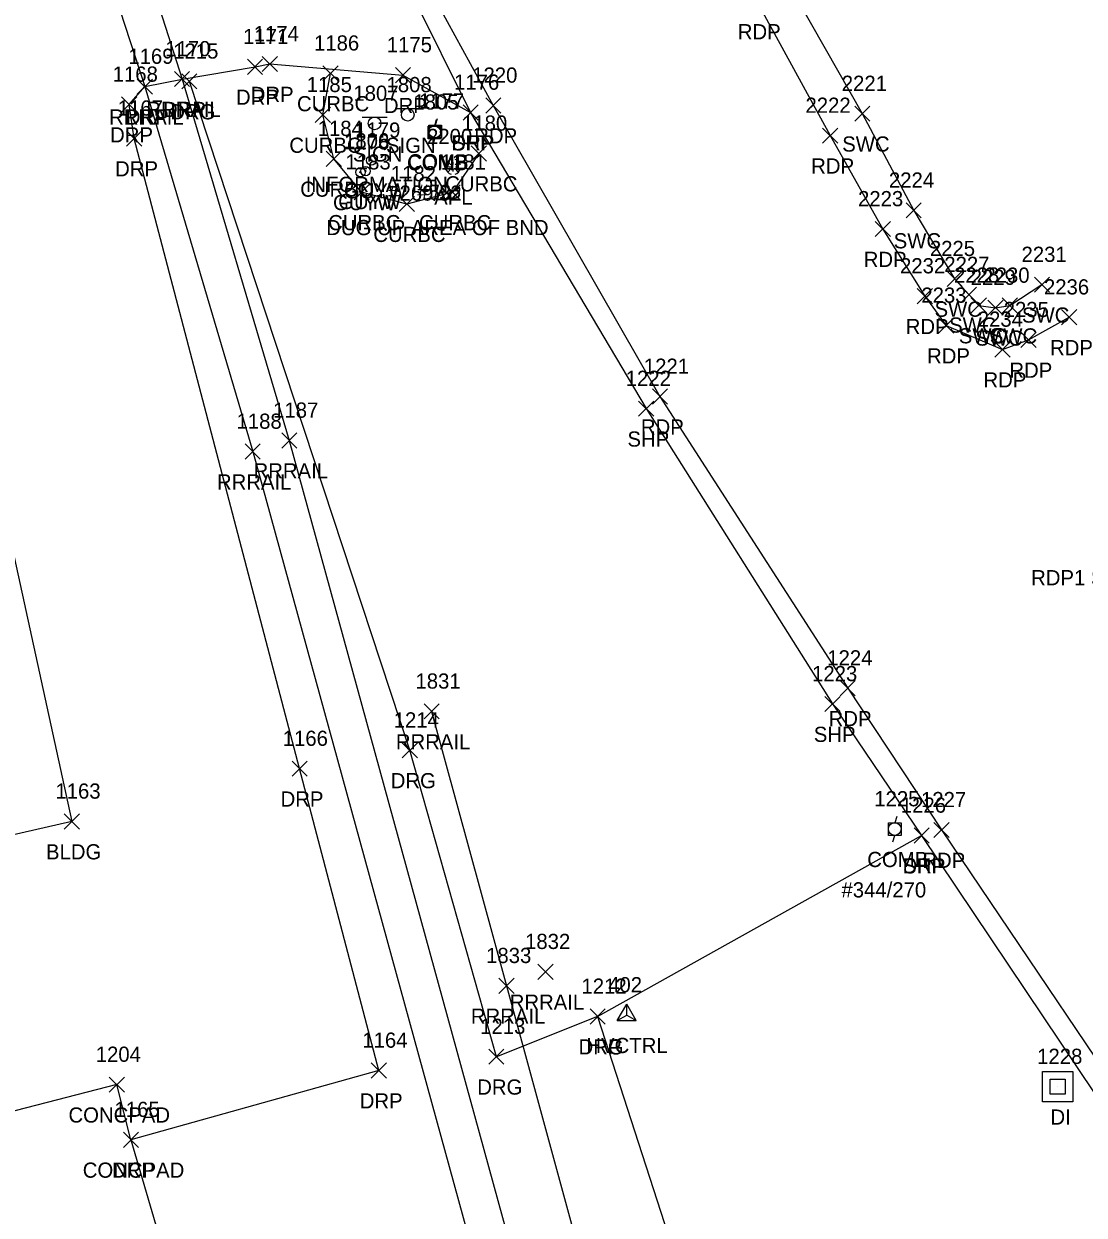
# Model space of a CAD drawing. Extents: x 1635588 to 1637550, y 621583 to 623638.
# Drawn here: x 1636495.2 to 1636634.9, y 622780.1 to 622937 of the extents above; entities that cross this region are included whole.
import ezdxf

# ---------------------------------------------------------------- set-up
doc = ezdxf.new("R2010")
doc.units = 0
for name, color, linetype in [('C_A', 7, 'Continuous'), ('C_I', 7, 'Continuous'), ('CPSM', 7, 'Continuous'), ('D_A', 7, 'Continuous'), ('D_I', 7, 'Continuous'), ('Default', 7, 'Continuous'), ('DS', 7, 'Continuous'), ('L_A', 7, 'Continuous'), ('L_I', 7, 'Continuous'), ('L_TIC', 7, 'Continuous'), ('LBC', 7, 'Continuous'), ('LS', 7, 'Continuous'), ('M_A', 7, 'Continuous'), ('M_C', 7, 'Continuous'), ('M_I', 7, 'Continuous'), ('P_A', 7, 'Continuous'), ('P_I', 7, 'Continuous'), ('P_TIC', 7, 'Continuous'), ('PET', 7, 'Continuous'), ('PSP', 7, 'Continuous'), ('R_A', 7, 'Continuous'), ('R_I', 7, 'Continuous'), ('R_TIC', 7, 'Continuous'), ('RC', 7, 'Continuous'), ('RDG', 7, 'Continuous'), ('RDP', 7, 'Continuous'), ('RR', 7, 'Continuous'), ('RSW', 7, 'Continuous'), ('S_A', 7, 'Continuous'), ('S_C', 7, 'Continuous'), ('S_I', 7, 'Continuous'), ('SSGN', 7, 'Continuous'), ('U_A', 7, 'Continuous'), ('U_C', 7, 'Continuous'), ('U_I', 7, 'Continuous'), ('UP', 7, 'Continuous'), ('UPGW', 7, 'Continuous')]:
    doc.layers.add(name, color=color, linetype=linetype)

msp = doc.modelspace()

# ---------------------------------------------------------------- linework, layer by layer
at = {"layer": 'CPSM'}
for p, q in [((1636573.37, 622805.72), (1636574.62, 622807.88)), ((1636575.87, 622805.72), (1636574.62, 622807.88)), ((1636574.62, 622806.44), (1636574.62, 622807.88)), ((1636573.37, 622805.72), (1636574.62, 622806.44)), ((1636574.62, 622806.44), (1636574.62, 622806.44)), ((1636574.62, 622806.44), (1636575.87, 622805.72)), ((1636573.37, 622805.72), (1636575.87, 622805.72))]:
    msp.add_line(p, q, dxfattribs=at)
at = {"layer": 'Default'}
for p, q in [((1636551.12, 622918.79), (1636551.48, 622918.43)), ((1636551.12, 622917.51), (1636551.48, 622917.87)), ((1636551.16, 622918.15), (1636551.46, 622918.15)), ((1636551.76, 622918.45), (1636551.76, 622918.75)), ((1636551.76, 622917.55), (1636551.76, 622917.85)), ((1636552.04, 622918.43), (1636552.4, 622918.79)), ((1636552.04, 622917.87), (1636552.4, 622917.51)), ((1636552.06, 622918.15), (1636552.36, 622918.15))]:
    msp.add_line(p, q, dxfattribs=at)
for start, end in [(105, 165), (15, 75), (195, 255), (285, 345)]:
    msp.add_arc((1636551.76, 622918.15), 1, start, end, dxfattribs=at)
at = {"layer": 'DS'}
for p, q in [((1636629.36, 622799.01), (1636633.36, 622799.01)), ((1636629.36, 622795.01), (1636629.36, 622799.01)), ((1636633.36, 622799.01), (1636633.36, 622795.01)), ((1636630.36, 622796.01), (1636630.36, 622798.01)), ((1636630.36, 622798.01), (1636632.36, 622798.01)), ((1636631.37, 622797.01), (1636631.37, 622797.01)), ((1636631.37, 622797.01), (1636631.37, 622797.01)), ((1636632.36, 622798.01), (1636632.36, 622796.01)), ((1636633.36, 622795.01), (1636629.36, 622795.01)), ((1636632.36, 622796.01), (1636630.36, 622796.01))]:
    msp.add_line(p, q, dxfattribs=at)
at = {"layer": 'L_TIC'}
for points in [[(1636500.57, 622830.94), (1636502.57, 622832.94)], [(1636502.57, 622830.94), (1636500.57, 622832.94)], [(1636506.48, 622796.28), (1636508.48, 622798.28)], [(1636508.48, 622796.28), (1636506.48, 622798.28)], [(1636508.35, 622789.02), (1636510.35, 622791.02)], [(1636510.35, 622789.02), (1636508.35, 622791.02)]]:
    msp.add_lwpolyline(points, dxfattribs=at)
at = {"layer": 'LBC'}
msp.add_lwpolyline([(1636457.17, 622910.42), (1636483.13, 622916.29), (1636501.57, 622831.94), (1636475.81, 622826.06), (1636457.17, 622910.42)], dxfattribs=at)
at = {"layer": 'LS'}
for points in [[(1636509.35, 622790.02), (1636507.48, 622797.28), (1636472.93, 622788.38)], [(1636509.35, 622790.02), (1636517.39, 622762.42)]]:
    msp.add_lwpolyline(points, dxfattribs=at)
at = {"layer": 'P_TIC'}
for points in [[(1636556.06, 622925.23), (1636558.06, 622927.23)], [(1636558.06, 622925.23), (1636556.06, 622927.23)], [(1636553.07, 622924.3), (1636555.07, 622926.3)], [(1636555.07, 622924.3), (1636553.07, 622926.3)], [(1636600.42, 622921.26), (1636602.42, 622923.26)], [(1636602.42, 622921.26), (1636600.42, 622923.26)], [(1636607.34, 622908.96), (1636609.34, 622910.96)], [(1636609.34, 622908.96), (1636607.34, 622910.96)], [(1636612.87, 622900.12), (1636614.87, 622902.12)], [(1636614.87, 622900.12), (1636612.87, 622902.12)], [(1636631.87, 622897.34), (1636633.87, 622899.34)], [(1636633.87, 622897.34), (1636631.87, 622899.34)], [(1636615.68, 622896.25), (1636617.68, 622898.25)], [(1636617.68, 622896.25), (1636615.68, 622898.25)], [(1636626.52, 622894.36), (1636628.52, 622896.36)], [(1636628.52, 622894.36), (1636626.52, 622896.36)], [(1636623.11, 622893.09), (1636625.11, 622895.09)], [(1636625.11, 622893.09), (1636623.11, 622895.09)], [(1636578, 622886.89), (1636580, 622888.89)], [(1636580, 622886.89), (1636578, 622888.89)], [(1636576.18, 622885.3), (1636578.18, 622887.3)], [(1636578.18, 622885.3), (1636576.18, 622887.3)], [(1636602.72, 622848.48), (1636604.72, 622850.48)], [(1636604.72, 622848.48), (1636602.72, 622850.48)], [(1636600.72, 622846.41), (1636602.72, 622848.41)], [(1636602.72, 622846.41), (1636600.72, 622848.41)], [(1636612.46, 622829.09), (1636614.46, 622831.09)], [(1636614.46, 622829.09), (1636612.46, 622831.09)], [(1636615.07, 622829.82), (1636617.07, 622831.82)], [(1636617.07, 622829.82), (1636615.07, 622831.82)]]:
    msp.add_lwpolyline(points, dxfattribs=at)
at = {"layer": 'PET'}
for points in [[(1636524.76, 623078.53), (1636523.53, 623074.7), (1636523.65, 623069.69), (1636530.21, 623056.13), (1636548.33, 623020.32), (1636566.47, 622984.44), (1636591.76, 622939.94), (1636601.42, 622922.26), (1636608.34, 622909.96), (1636613.87, 622901.12), (1636616.68, 622897.25), (1636624.11, 622894.09), (1636627.52, 622895.36), (1636632.87, 622898.34)], [(1636496.54, 623045.3), (1636533.69, 622970.65), (1636546.95, 622944.69), (1636557.06, 622926.23), (1636579, 622887.89), (1636603.72, 622849.48), (1636616.07, 622830.82), (1636647.79, 622783.76), (1636703.25, 622700.68), (1636737.08, 622649.81), (1636763.83, 622609.67), (1636812.95, 622535.62), (1636858.06, 622468.21), (1636878.24, 622438.26), (1636911.18, 622389.38), (1636974.88, 622293.33), (1636986.61, 622276.7), (1637016.63, 622231.99)]]:
    msp.add_lwpolyline(points, dxfattribs=at)
at = {"layer": 'PSP'}
msp.add_lwpolyline([(1636412.61, 623220.07), (1636436.6, 623167.3), (1636456.23, 623125.07), (1636460.67, 623115.98), (1636475.52, 623084.87), (1636494.51, 623045.42), (1636524.16, 622986.51), (1636530.74, 622972.24), (1636554.07, 622925.3), (1636577.18, 622886.3), (1636601.72, 622847.41), (1636613.46, 622830.09), (1636645.38, 622782.47), (1636700.61, 622698.86), (1636734.28, 622648.07), (1636752.12, 622619.3), (1636752.46, 622616.81), (1636755.34, 622613.42), (1636810.04, 622534.39), (1636855.63, 622465.66), (1636874.76, 622437.49), (1636904.15, 622393.55)], dxfattribs=at)
at = {"layer": 'R_TIC'}
for points in [[(1636524.68, 622930.32), (1636526.68, 622932.32)], [(1636526.68, 622930.32), (1636524.68, 622932.32)], [(1636526.63, 622930.69), (1636528.63, 622932.69)], [(1636528.63, 622930.69), (1636526.63, 622932.69)], [(1636534.63, 622929.46), (1636536.63, 622931.46)], [(1636536.63, 622929.46), (1636534.63, 622931.46)], [(1636515.07, 622928.71), (1636517.07, 622930.71)], [(1636517.07, 622928.71), (1636515.07, 622930.71)], [(1636515.07, 622928.71), (1636517.07, 622930.71)], [(1636517.07, 622928.71), (1636515.07, 622930.71)], [(1636516.04, 622928.4), (1636518.04, 622930.4)], [(1636518.04, 622928.4), (1636516.04, 622930.4)], [(1636544.16, 622929.23), (1636546.16, 622931.23)], [(1636546.16, 622929.23), (1636544.16, 622931.23)], [(1636510.18, 622927.71), (1636512.18, 622929.71)], [(1636512.18, 622927.71), (1636510.18, 622929.71)], [(1636510.18, 622927.71), (1636512.18, 622929.71)], [(1636512.18, 622927.71), (1636510.18, 622929.71)], [(1636508.11, 622925.36), (1636510.11, 622927.36)], [(1636510.11, 622925.36), (1636508.11, 622927.36)], [(1636533.61, 622923.99), (1636535.61, 622925.99)], [(1636535.61, 622923.99), (1636533.61, 622925.99)], [(1636553.07, 622924.3), (1636555.07, 622926.3)], [(1636555.07, 622924.3), (1636553.07, 622926.3)], [(1636604.64, 622924.15), (1636606.64, 622926.15)], [(1636606.64, 622924.15), (1636604.64, 622926.15)], [(1636508.77, 622920.89), (1636510.77, 622922.89)], [(1636510.77, 622920.89), (1636508.77, 622922.89)], [(1636554.15, 622918.91), (1636556.15, 622920.91)], [(1636556.15, 622918.91), (1636554.15, 622920.91)], [(1636535.05, 622918.21), (1636537.05, 622920.21)], [(1636537.05, 622918.21), (1636535.05, 622920.21)], [(1636538.72, 622913.8), (1636540.72, 622915.8)], [(1636540.72, 622913.8), (1636538.72, 622915.8)], [(1636550.69, 622913.79), (1636552.69, 622915.79)], [(1636552.69, 622913.79), (1636550.69, 622915.79)], [(1636544.68, 622912.25), (1636546.68, 622914.25)], [(1636546.68, 622912.25), (1636544.68, 622914.25)], [(1636611.41, 622911.41), (1636613.41, 622913.41)], [(1636613.41, 622911.41), (1636611.41, 622913.41)], [(1636616.8, 622902.4), (1636618.8, 622904.4)], [(1636618.8, 622902.4), (1636616.8, 622904.4)], [(1636628.3, 622901.63), (1636630.3, 622903.63)], [(1636630.3, 622901.63), (1636628.3, 622903.63)], [(1636618.7, 622900.31), (1636620.7, 622902.31)], [(1636620.7, 622900.31), (1636618.7, 622902.31)], [(1636619.99, 622898.9), (1636621.99, 622900.9)], [(1636621.99, 622898.9), (1636619.99, 622900.9)], [(1636622.17, 622898.6), (1636624.17, 622900.6)], [(1636624.17, 622898.6), (1636622.17, 622900.6)], [(1636624.06, 622898.88), (1636626.06, 622900.88)], [(1636626.06, 622898.88), (1636624.06, 622900.88)], [(1636529.2, 622881.11), (1636531.2, 622883.11)], [(1636531.2, 622881.11), (1636529.2, 622883.11)], [(1636524.38, 622879.65), (1636526.38, 622881.65)], [(1636526.38, 622879.65), (1636524.38, 622881.65)], [(1636547.94, 622845.43), (1636549.94, 622847.43)], [(1636549.94, 622845.43), (1636547.94, 622847.43)], [(1636545.06, 622840.31), (1636547.06, 622842.31)], [(1636547.06, 622840.31), (1636545.06, 622842.31)], [(1636530.56, 622837.89), (1636532.56, 622839.89)], [(1636532.56, 622837.89), (1636530.56, 622839.89)], [(1636612.46, 622829.09), (1636614.46, 622831.09)], [(1636614.46, 622829.09), (1636612.46, 622831.09)], [(1636562.93, 622811.14), (1636564.93, 622813.14)], [(1636564.93, 622811.14), (1636562.93, 622813.14)], [(1636557.8, 622809.29), (1636559.8, 622811.29)], [(1636559.8, 622809.29), (1636557.8, 622811.29)], [(1636569.79, 622805.25), (1636571.79, 622807.25)], [(1636571.79, 622805.25), (1636569.79, 622807.25)], [(1636569.79, 622805.25), (1636571.79, 622807.25)], [(1636571.79, 622805.25), (1636569.79, 622807.25)], [(1636569.79, 622805.25), (1636571.79, 622807.25)], [(1636571.79, 622805.25), (1636569.79, 622807.25)], [(1636556.46, 622799.96), (1636558.46, 622801.96)], [(1636558.46, 622799.96), (1636556.46, 622801.96)], [(1636540.98, 622798.14), (1636542.98, 622800.14)], [(1636542.98, 622798.14), (1636540.98, 622800.14)], [(1636540.98, 622798.14), (1636542.98, 622800.14)], [(1636542.98, 622798.14), (1636540.98, 622800.14)], [(1636508.35, 622789.02), (1636510.35, 622791.02)], [(1636510.35, 622789.02), (1636508.35, 622791.02)]]:
    msp.add_lwpolyline(points, dxfattribs=at)
at = {"layer": 'RC'}
msp.add_lwpolyline([(1636555.15, 622919.91), (1636551.69, 622914.79), (1636545.68, 622913.25), (1636539.72, 622914.8), (1636536.05, 622919.21), (1636534.61, 622924.99), (1636535.63, 622930.46)], dxfattribs=at)
at = {"layer": 'RDG'}
msp.add_lwpolyline([(1636570.79, 622806.25), (1636557.46, 622800.96), (1636546.06, 622841.31), (1636517.04, 622929.4)], dxfattribs=at)
at = {"layer": 'RDP'}
for points in [[(1636541.98, 622799.14), (1636531.56, 622838.89), (1636509.77, 622921.89), (1636509.11, 622926.36), (1636511.18, 622928.71), (1636516.07, 622929.71), (1636525.68, 622931.32), (1636527.63, 622931.69), (1636545.16, 622930.23), (1636554.07, 622925.3)], [(1636570.79, 622806.25), (1636613.46, 622830.09)], [(1636570.79, 622806.25), (1636586.44, 622757.82), (1636599.97, 622709.22), (1636612.89, 622647.59)], [(1636541.98, 622799.14), (1636509.35, 622790.02)]]:
    msp.add_lwpolyline(points, dxfattribs=at)
at = {"layer": 'RR'}
for points in [[(1636406.43, 623208.62), (1636424.65, 623171.19), (1636442.27, 623131.47), (1636462.36, 623079.17), (1636475.1, 623045.34), (1636499.5, 622979.8), (1636509.41, 622950.55), (1636516.07, 622929.71), (1636530.2, 622882.11), (1636568.93, 622740.93), (1636580.62, 622697.82)], [(1636401.96, 623205.78), (1636420.49, 623168.36), (1636437.73, 623129.25), (1636458.96, 623074.5), (1636470.76, 623043.73), (1636495.27, 622977.34), (1636504.04, 622950.72), (1636511.18, 622928.71), (1636525.38, 622880.65), (1636564.25, 622739.19), (1636576, 622696.58)], [(1636548.94, 622846.43), (1636558.8, 622810.29), (1636577.63, 622741.25), (1636594.59, 622680.12), (1636616.94, 622598.07), (1636625.5, 622566.08)]]:
    msp.add_lwpolyline(points, dxfattribs=at)
at = {"layer": 'RSW'}
msp.add_lwpolyline([(1636524.76, 623078.53), (1636528.35, 623071.35), (1636530.25, 623067.42), (1636534.71, 623058.46), (1636552.77, 623022.45), (1636571.37, 622985.37), (1636595.71, 622942.66), (1636605.64, 622925.15), (1636612.41, 622912.41), (1636617.8, 622903.4), (1636619.7, 622901.31), (1636620.99, 622899.9), (1636623.17, 622899.6), (1636625.06, 622899.88), (1636629.3, 622902.63)], dxfattribs=at)
at = {"layer": 'SSGN'}
for p, q in [((1636544.14, 622925.83), (1636547.48, 622925.83)), ((1636539.77, 622924.7), (1636543.1, 622924.7)), ((1636541.42, 622923.86), (1636541.42, 622923.86)), ((1636545.79, 622925), (1636545.79, 622925))]:
    msp.add_line(p, q, dxfattribs=at)
for centre in [(1636545.79, 622925), (1636541.42, 622923.86)]:
    msp.add_circle(centre, 0.833, dxfattribs=at)
at = {"layer": 'UP'}
for p, q in [((1636548.56, 622921.98), (1636548.56, 622923.65)), ((1636548.56, 622923.65), (1636550.23, 622923.65)), ((1636549.55, 622924.35), (1636549.3, 622923.52)), ((1636549.65, 622924.48), (1636549.4, 622923.65)), ((1636550.23, 622923.65), (1636550.23, 622921.98)), ((1636548.47, 622921.85), (1636548.47, 622923.52)), ((1636548.47, 622923.52), (1636550.14, 622923.52)), ((1636549.3, 622922.69), (1636549.3, 622922.69)), ((1636549.4, 622922.81), (1636549.4, 622922.81)), ((1636550.14, 622923.52), (1636550.14, 622921.85)), ((1636550.14, 622921.85), (1636548.47, 622921.85)), ((1636550.23, 622921.98), (1636548.56, 622921.98)), ((1636549.05, 622921.02), (1636549.3, 622921.85)), ((1636549.15, 622921.15), (1636549.4, 622921.98)), ((1636610.17, 622832.6), (1636609.92, 622831.77)), ((1636609.08, 622830.1), (1636609.08, 622831.77)), ((1636609.08, 622831.77), (1636610.75, 622831.77)), ((1636610.75, 622831.77), (1636610.75, 622830.1)), ((1636610.75, 622830.1), (1636609.08, 622830.1)), ((1636609.67, 622829.27), (1636609.92, 622830.1)), ((1636609.92, 622830.93), (1636609.92, 622830.93))]:
    msp.add_line(p, q, dxfattribs=at)
for centre in [(1636549.4, 622922.81), (1636549.3, 622922.69), (1636609.92, 622830.93)]:
    msp.add_circle(centre, 0.833, dxfattribs=at)
at = {"layer": 'UPGW'}
for centre, radius in [((1636541, 622918.99), 0.625), ((1636541, 622918.99), 0.0833), ((1636539.56, 622917.44), 0.625), ((1636539.56, 622917.44), 0.0833), ((1636540.23, 622917.58), 0.625), ((1636540.23, 622917.58), 0.0833)]:
    msp.add_circle(centre, radius, dxfattribs=at)

# ---------------------------------------------------------------- texts
at = {"layer": 'C_A'}
msp.add_text('HVCTRL', height=2, dxfattribs=at).set_placement((1636569.32, 622801.44))
at = {"layer": 'C_I'}
msp.add_text('402', height=2, dxfattribs=at).set_placement((1636572.18, 622809.44))
at = {"layer": 'D_A'}
msp.add_text('DI', height=2, dxfattribs=at).set_placement((1636630.42, 622792.01))
at = {"layer": 'D_I'}
msp.add_text('1228', height=2, dxfattribs=at).set_placement((1636628.67, 622800.01))
at = {"layer": 'L_A'}
for s, p in [('BLDG', (1636498.16, 622826.94)), ('CONCPAD', (1636501.12, 622792.28)), ('CONCPAD', (1636503, 622785.02))]:
    msp.add_text(s, height=2, dxfattribs=at).set_placement(p)
at = {"layer": 'L_I'}
for s, p in [('1163', (1636499.4, 622834.94)), ('1204', (1636504.71, 622800.28)), ('1165', (1636507.18, 622793.02))]:
    msp.add_text(s, height=2, dxfattribs=at).set_placement(p)
at = {"layer": 'M_A'}
msp.add_text('APL', height=2, dxfattribs=at).set_placement((1636549.27, 622913.15))
at = {"layer": 'M_C'}
msp.add_text('DUG UP AREA OF BND', height=2, dxfattribs=at).set_placement((1636535.06, 622909.15))
at = {"layer": 'M_I'}
msp.add_text('2200', height=2, dxfattribs=at).set_placement((1636548.33, 622921.15))
at = {"layer": 'P_A'}
for s, p in [('RDP', (1636589.25, 622934.94)), ('SHP', (1636551.6, 622920.3)), ('RDP', (1636554.55, 622921.23)), ('RDP', (1636598.91, 622917.26)), ('RDP', (1636605.83, 622904.96)), ('RDP', (1636611.36, 622896.12)), ('RDP', (1636614.17, 622892.25)), ('RDP', (1636630.36, 622893.34)), ('RDP', (1636625.01, 622890.36)), ('RDP', (1636621.6, 622889.09)), ('RDP', (1636576.49, 622882.89)), ('SHP', (1636574.72, 622881.3)), ('RDP', (1636601.21, 622844.48)), ('SHP', (1636599.26, 622842.41)), ('SHP', (1636611, 622825.09)), ('RDP', (1636613.55, 622825.82))]:
    msp.add_text(s, height=2, dxfattribs=at).set_placement(p)
at = {"layer": 'P_I'}
for s, p in [('1176', (1636551.89, 622928.3)), ('1220', (1636554.28, 622929.23)), ('2222', (1636598.16, 622925.26)), ('2223', (1636605.08, 622912.96)), ('2232', (1636610.61, 622904.12)), ('2236', (1636629.56, 622901.34)), ('2233', (1636613.42, 622900.25)), ('2235', (1636624.26, 622898.36)), ('2234', (1636620.85, 622897.09)), ('1221', (1636576.88, 622890.89)), ('1222', (1636574.49, 622889.3)), ('1224', (1636601.03, 622852.48)), ('1223', (1636599.03, 622850.41)), ('1227', (1636613.37, 622833.82)), ('1226', (1636610.72, 622833.09))]:
    msp.add_text(s, height=2, dxfattribs=at).set_placement(p)
at = {"layer": 'R_A'}
for s, p in [('DRP', (1636523.17, 622926.32)), ('DRP', (1636525.12, 622926.69)), ('CURBC', (1636531.21, 622925.46)), ('DRP', (1636542.65, 622925.23)), ('RRRAIL', (1636506.47, 622923.71)), ('DRP', (1636508.67, 622923.71)), ('RRRAIL', (1636511.36, 622924.71)), ('DRP', (1636513.56, 622924.71)), ('DRG', (1636514.53, 622924.4)), ('DRP', (1636506.6, 622921.36)), ('CURBC', (1636530.2, 622919.99)), ('DRP', (1636551.55, 622920.3)), ('SWC', (1636603, 622920.15)), ('DRP', (1636507.26, 622916.89)), ('CURBC', (1636531.63, 622914.21)), ('CURBC', (1636550.73, 622914.91)), ('CURBC', (1636535.31, 622909.8)), ('CURBC', (1636547.27, 622909.79)), ('CURBC', (1636541.26, 622908.25)), ('SWC', (1636609.78, 622907.41)), ('SWC', (1636615.16, 622898.4)), ('SWC', (1636626.67, 622897.63)), ('SWC', (1636617.07, 622896.31)), ('SWC', (1636618.35, 622894.9)), ('SWC', (1636620.54, 622894.6)), ('SWC', (1636622.43, 622894.88)), ('RRRAIL', (1636525.49, 622877.11)), ('RRRAIL', (1636520.67, 622875.65)), ('RDP1 ST SWC ST', (1636627.87, 622863.04)), ('RRRAIL', (1636544.23, 622841.43)), ('DRG', (1636543.55, 622836.31)), ('DRP', (1636529.05, 622833.89)), ('DRP', (1636610.95, 622825.09)), ('RRRAIL', (1636559.22, 622807.14)), ('RRRAIL', (1636554.1, 622805.29)), ('DRG', (1636568.28, 622801.25)), ('DRP', (1636568.28, 622801.25)), ('DRP', (1636568.28, 622801.25)), ('DRG', (1636554.94, 622795.96)), ('DRP', (1636539.47, 622794.14)), ('DRP', (1636539.47, 622794.14)), ('DRP', (1636506.84, 622785.02))]:
    msp.add_text(s, height=2, dxfattribs=at).set_placement(p)
at = {"layer": 'R_I'}
for s, p in [('1171', (1636524.12, 622934.32)), ('1174', (1636525.5, 622934.69)), ('1170', (1636513.86, 622932.71)), ('1170', (1636513.86, 622932.71)), ('1186', (1636533.45, 622933.46)), ('1175', (1636543.03, 622933.23)), ('1169', (1636509, 622931.71)), ('1169', (1636509, 622931.71)), ('1215', (1636514.91, 622932.4)), ('1168', (1636506.94, 622929.36)), ('1185', (1636532.49, 622927.99)), ('1176', (1636551.89, 622928.3)), ('2221', (1636602.94, 622928.15)), ('1167', (1636507.6, 622924.89)), ('1184', (1636533.93, 622922.21)), ('1180', (1636552.94, 622922.91)), ('1183', (1636537.6, 622917.8)), ('1181', (1636550.13, 622917.79)), ('1182', (1636543.56, 622916.25)), ('2224', (1636609.15, 622915.41)), ('2225', (1636614.54, 622906.4)), ('2227', (1636616.44, 622904.31)), ('2231', (1636626.61, 622905.63)), ('2228', (1636617.73, 622902.9)), ('2230', (1636621.72, 622902.88)), ('2229', (1636619.91, 622902.6)), ('1187', (1636528.07, 622885.11)), ('1188', (1636523.25, 622883.65)), ('1831', (1636546.81, 622849.43)), ('1214', (1636543.94, 622844.31)), ('1166', (1636529.33, 622841.89)), ('1226', (1636610.72, 622833.09)), ('1832', (1636561.24, 622815.14)), ('1833', (1636556.11, 622813.29)), ('1212', (1636568.67, 622809.25)), ('1212', (1636568.67, 622809.25)), ('1212', (1636568.67, 622809.25)), ('1213', (1636555.33, 622803.96)), ('1164', (1636539.81, 622802.14)), ('1164', (1636539.81, 622802.14)), ('1165', (1636507.18, 622793.02))]:
    msp.add_text(s, height=2, dxfattribs=at).set_placement(p)
at = {"layer": 'S_A'}
for p in [(1636538.56, 622918.84), (1636542.93, 622919.98)]:
    msp.add_text('SIGN', height=2, dxfattribs=at).set_placement(p)
at = {"layer": 'S_C'}
msp.add_text('INFORMATION', height=2, dxfattribs=at).set_placement((1636532.35, 622914.84))
at = {"layer": 'S_I'}
for s, p in [('1808', (1636543, 622927.98)), ('1807', (1636538.63, 622926.84))]:
    msp.add_text(s, height=2, dxfattribs=at).set_placement(p)
at = {"layer": 'U_A'}
for s, p in [('COMB', (1636545.69, 622917.69)), ('COMB', (1636545.78, 622917.81)), ('GUYW', (1636537.39, 622913.99)), ('GUYW', (1636535.95, 622912.44)), ('GUYW', (1636536.63, 622912.58)), ('COMB', (1636606.3, 622825.93))]:
    msp.add_text(s, height=2, dxfattribs=at).set_placement(p)
at = {"layer": 'U_C'}
for s, p in [('#269/52', (1636543.22, 622913.69)), ('#52', (1636547.04, 622913.81)), ('#344/270', (1636602.9, 622821.93))]:
    msp.add_text(s, height=2, dxfattribs=at).set_placement(p)
at = {"layer": 'U_I'}
for s, p in [('1805', (1636546.53, 622925.69)), ('1177', (1636547.27, 622925.81)), ('1179', (1636538.87, 622921.99)), ('1806', (1636537.41, 622920.58)), ('1178', (1636537.43, 622920.44)), ('1225', (1636607.22, 622833.93))]:
    msp.add_text(s, height=2, dxfattribs=at).set_placement(p)

doc.saveas('drawing.dxf')
